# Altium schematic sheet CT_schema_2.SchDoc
size 186 x 134 mm
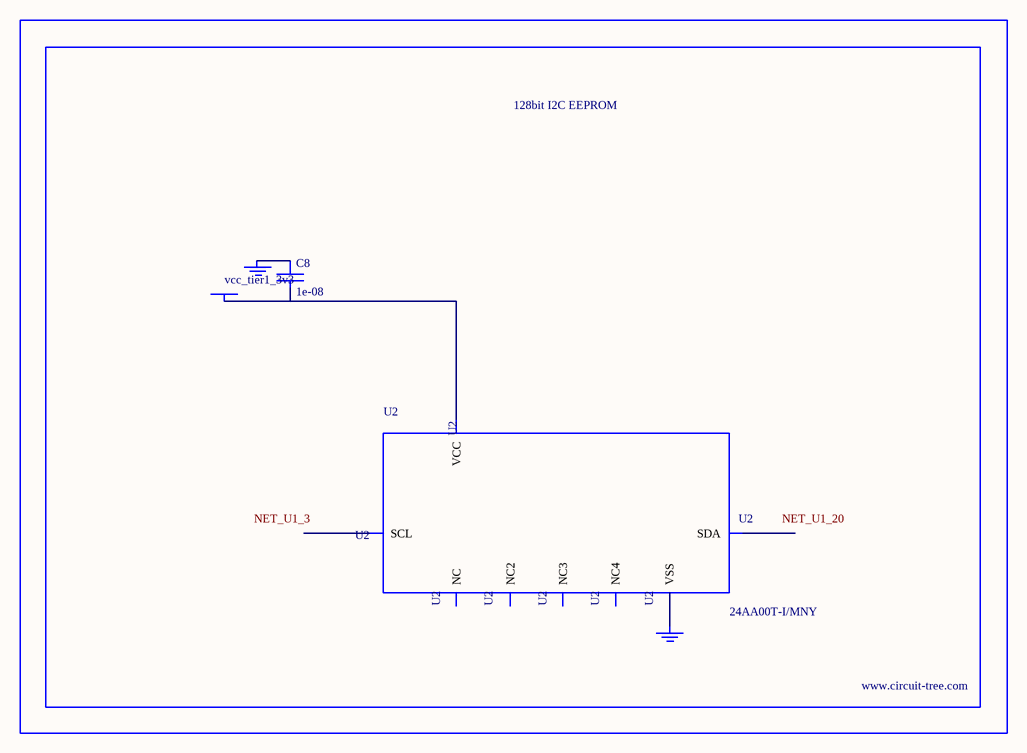
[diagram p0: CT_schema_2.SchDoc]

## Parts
BORDER1  (no value)
C8  1e-08  [C0402]
GND_INSTANCE_1_0  (no value)
GND_INSTANCE_1_1  (no value)
POWER_INSTANCE_1_0  vcc_tier1_3v3
U2  24AA00T-I/MNY  [TDFN-8/6MM]

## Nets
NetC8_1: C8.1 GND_INSTANCE_1_0.0(GND)
NetC8_2: C8.2 POWER_INSTANCE_1_0.0(PWR) U2.8(VCC)
NetGND_INSTANCE_1_1_0: GND_INSTANCE_1_1.0(GND) U2.4(VSS)

Not connected (* = marked no-connect by the designer): U2 1(NC) 2(NC2) 3(NC3) 5(SDA) 6(SCL) 7(NC4)

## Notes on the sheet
- Labels drawn without touching a wire or pin: NET_U1_3, NET_U1_20

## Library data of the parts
BORDER1 = BORDER_PAGE1
C8 = C0402C103K3RAC
GND_INSTANCE_1_0 GND_INSTANCE_1_1 = GND
POWER_INSTANCE_1_0 = PWR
